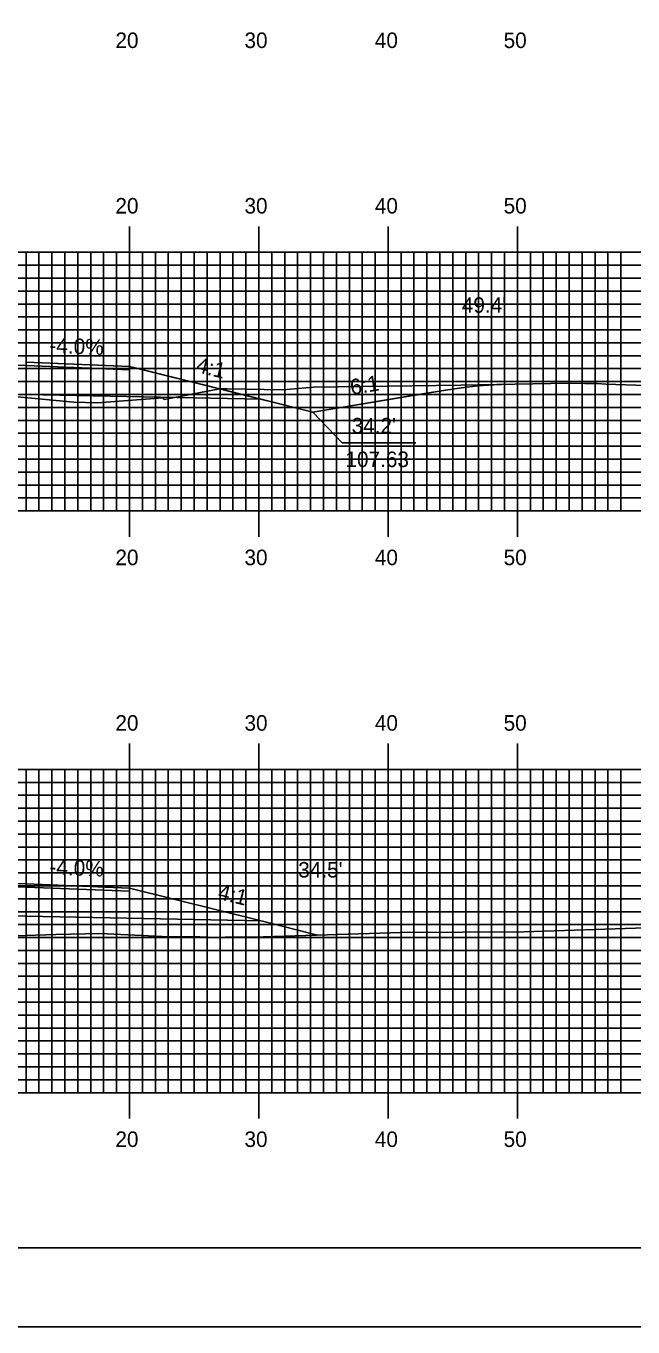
# Model space of a CAD drawing. Extents: x 1766120 to 1766463, y 442591 to 442811.
# Drawn here: x 1766297.4 to 1766344.3, y 442590.5 to 442691.2 of the extents above; entities that cross this region are included whole.
import ezdxf

# ---------------------------------------------------------------- set-up
doc = ezdxf.new("R2010")
doc.units = 0
for name, color, linetype in [('ANNOTATION', 7, 'Continuous'), ('BORDER', 7, 'Continuous'), ('D_Roadway_Centerline', 7, 'Continuous'), ('D_Roadway_Edge_Shoulder', 7, 'Continuous'), ('D_Roadway_SlopeLines', 7, 'Continuous'), ('D_Roadway_SubGrade', 7, 'Continuous'), ('D_Text_Standard', 7, 'Continuous'), ('H_V ANNOTATION', 7, 'Continuous'), ('MAJOR', 7, 'Continuous'), ('MINOR', 7, 'Continuous'), ('PLOT BOUNDARY', 7, 'Continuous'), ('S_Roadway_Centerline', 7, 'Continuous')]:
    doc.layers.add(name, color=color, linetype=linetype)

msp = doc.modelspace()

# ---------------------------------------------------------------- linework, layer by layer
at = {"layer": 'ANNOTATION'}
msp.add_lwpolyline([(1766327.54, 442658.93), (1766321.85, 442658.93), (1766319.57, 442661.3)], dxfattribs=at)
at = {"layer": 'BORDER'}
msp.add_lwpolyline([(1766135.8, 442596.67), (1766455.8, 442596.67), (1766455.8, 442806.67), (1766135.8, 442806.67)], close=True, dxfattribs=at)
at = {"layer": 'D_Roadway_Centerline'}
for points in [[(1766297.4, 442665.16), (1766305.4, 442664.84), (1766306.38, 442664.6), (1766315.57, 442662.3), (1766315.57, 442662.3), (1766315.57, 442662.3), (1766319.57, 442661.3), (1766328.22, 442662.74), (1766329.83, 442663.01), (1766331.08, 442663.19), (1766332.33, 442663.33), (1766333.58, 442663.42), (1766334.83, 442663.46)], [(1766244.99, 442619.92), (1766247.79, 442620.62), (1766253.4, 442622.03), (1766253.4, 442622.03), (1766255.22, 442622.48), (1766255.23, 442622.48), (1766261.12, 442623.95), (1766265.4, 442625.03), (1766265.4, 442625.03), (1766273.4, 442625.35), (1766273.4, 442625.35), (1766285.4, 442625.08), (1766285.8, 442625.07), (1766297.39, 442624.82), (1766297.4, 442624.82), (1766305.4, 442624.5), (1766305.4, 442624.5), (1766305.4, 442624.5), (1766315.57, 442621.95), (1766319.93, 442620.86)]]:
    msp.add_lwpolyline(points, dxfattribs=at)
at = {"layer": 'D_Roadway_Edge_Shoulder'}
for points in [[(1766297.4, 442665.16), (1766305.4, 442664.84), (1766305.4, 442664.59), (1766297.4, 442664.91)], [(1766297.4, 442624.82), (1766305.4, 442624.5), (1766305.4, 442624.25), (1766297.4, 442624.57)]]:
    msp.add_lwpolyline(points, close=True, dxfattribs=at)
at = {"layer": 'D_Roadway_SlopeLines'}
for points in [[(1766305.4, 442664.84), (1766319.57, 442661.3)], [(1766319.57, 442661.3), (1766329.83, 442663.01), (1766331.08, 442663.19), (1766332.33, 442663.33), (1766333.58, 442663.42), (1766334.83, 442663.46)], [(1766305.4, 442624.5), (1766315.57, 442621.95), (1766319.93, 442620.86)]]:
    msp.add_lwpolyline(points, dxfattribs=at)
at = {"layer": 'D_Roadway_SubGrade'}
for points in [[(1766273.4, 442663.19), (1766255.22, 442662.83), (1766265.4, 442665.37), (1766265.4, 442665.12), (1766273.4, 442665.44), (1766285.4, 442665.17), (1766297.4, 442664.91), (1766305.4, 442664.59), (1766305.4, 442664.84), (1766315.57, 442662.3), (1766297.4, 442662.66), (1766285.4, 442662.92)], [(1766273.4, 442622.85), (1766255.22, 442622.48), (1766265.4, 442625.03), (1766265.4, 442624.78), (1766273.4, 442625.1), (1766285.4, 442624.83), (1766297.4, 442624.57), (1766305.4, 442624.25), (1766305.4, 442624.5), (1766315.57, 442621.95), (1766297.4, 442622.32), (1766285.4, 442622.58)]]:
    msp.add_lwpolyline(points, close=True, dxfattribs=at)
at = {"layer": 'MAJOR'}
for p, q in [((1766305.4, 442675.67), (1766305.4, 442673.67)), ((1766315.4, 442675.67), (1766315.4, 442673.67)), ((1766325.4, 442675.67), (1766325.4, 442673.67)), ((1766335.4, 442675.67), (1766335.4, 442673.67)), ((1766145.4, 442673.67), (1766425.4, 442673.67)), ((1766145.4, 442673.67), (1766425.4, 442673.67)), ((1766305.4, 442653.67), (1766305.4, 442673.67)), ((1766315.4, 442653.67), (1766315.4, 442673.67)), ((1766325.4, 442653.67), (1766325.4, 442673.67)), ((1766335.4, 442653.67), (1766335.4, 442673.67)), ((1766145.4, 442668.67), (1766425.4, 442668.67)), ((1766145.4, 442663.67), (1766425.4, 442663.67)), ((1766145.4, 442658.67), (1766425.4, 442658.67)), ((1766145.4, 442653.67), (1766425.4, 442653.67)), ((1766145.4, 442653.67), (1766425.4, 442653.67)), ((1766305.4, 442651.66), (1766305.4, 442653.67)), ((1766315.4, 442651.66), (1766315.4, 442653.67)), ((1766325.4, 442651.66), (1766325.4, 442653.67)), ((1766335.4, 442651.66), (1766335.4, 442653.67)), ((1766305.4, 442635.67), (1766305.4, 442633.67)), ((1766315.4, 442635.67), (1766315.4, 442633.67)), ((1766325.4, 442635.67), (1766325.4, 442633.67)), ((1766335.4, 442635.67), (1766335.4, 442633.67)), ((1766145.4, 442633.67), (1766425.4, 442633.67)), ((1766145.4, 442633.67), (1766425.4, 442633.67)), ((1766305.4, 442608.67), (1766305.4, 442633.67)), ((1766315.4, 442608.67), (1766315.4, 442633.67)), ((1766325.4, 442608.67), (1766325.4, 442633.67)), ((1766335.4, 442608.67), (1766335.4, 442633.67)), ((1766145.4, 442628.67), (1766425.4, 442628.67)), ((1766145.4, 442623.67), (1766425.4, 442623.67)), ((1766145.4, 442618.67), (1766425.4, 442618.67)), ((1766145.4, 442613.67), (1766425.4, 442613.67)), ((1766145.4, 442608.67), (1766425.4, 442608.67)), ((1766145.4, 442608.67), (1766425.4, 442608.67)), ((1766305.4, 442606.66), (1766305.4, 442608.67)), ((1766315.4, 442606.66), (1766315.4, 442608.67)), ((1766325.4, 442606.66), (1766325.4, 442608.67)), ((1766335.4, 442606.66), (1766335.4, 442608.67))]:
    msp.add_line(p, q, dxfattribs=at)
at = {"layer": 'MINOR'}
for p, q in [((1766297.4, 442653.67), (1766297.4, 442673.67)), ((1766298.4, 442653.67), (1766298.4, 442673.67)), ((1766299.4, 442653.67), (1766299.4, 442673.67)), ((1766300.4, 442653.67), (1766300.4, 442673.67)), ((1766301.4, 442653.67), (1766301.4, 442673.67)), ((1766302.4, 442653.67), (1766302.4, 442673.67)), ((1766303.4, 442653.67), (1766303.4, 442673.67)), ((1766304.4, 442653.67), (1766304.4, 442673.67)), ((1766306.4, 442653.67), (1766306.4, 442673.67)), ((1766307.4, 442653.67), (1766307.4, 442673.67)), ((1766308.4, 442653.67), (1766308.4, 442673.67)), ((1766309.4, 442653.67), (1766309.4, 442673.67)), ((1766310.4, 442653.67), (1766310.4, 442673.67)), ((1766311.4, 442653.67), (1766311.4, 442673.67)), ((1766312.4, 442653.67), (1766312.4, 442673.67)), ((1766313.4, 442653.67), (1766313.4, 442673.67)), ((1766314.4, 442653.67), (1766314.4, 442673.67)), ((1766316.4, 442653.67), (1766316.4, 442673.67)), ((1766317.4, 442653.67), (1766317.4, 442673.67)), ((1766318.4, 442653.67), (1766318.4, 442673.67)), ((1766319.4, 442653.67), (1766319.4, 442673.67)), ((1766320.4, 442653.67), (1766320.4, 442673.67)), ((1766321.4, 442653.67), (1766321.4, 442673.67)), ((1766322.4, 442653.67), (1766322.4, 442673.67)), ((1766323.4, 442653.67), (1766323.4, 442673.67)), ((1766324.4, 442653.67), (1766324.4, 442673.67)), ((1766326.4, 442653.67), (1766326.4, 442673.67)), ((1766327.4, 442653.67), (1766327.4, 442673.67)), ((1766328.4, 442653.67), (1766328.4, 442673.67)), ((1766329.4, 442653.67), (1766329.4, 442673.67)), ((1766330.4, 442653.67), (1766330.4, 442673.67)), ((1766331.4, 442653.67), (1766331.4, 442673.67)), ((1766332.4, 442653.67), (1766332.4, 442673.67)), ((1766333.4, 442653.67), (1766333.4, 442673.67)), ((1766334.4, 442653.67), (1766334.4, 442673.67)), ((1766336.4, 442653.67), (1766336.4, 442673.67)), ((1766337.4, 442653.67), (1766337.4, 442673.67)), ((1766338.4, 442653.67), (1766338.4, 442673.67)), ((1766339.4, 442653.67), (1766339.4, 442673.67)), ((1766340.4, 442653.67), (1766340.4, 442673.67)), ((1766341.4, 442653.67), (1766341.4, 442673.67)), ((1766342.4, 442653.67), (1766342.4, 442673.67)), ((1766343.4, 442653.67), (1766343.4, 442673.67)), ((1766145.4, 442672.67), (1766425.4, 442672.67)), ((1766145.4, 442671.67), (1766425.4, 442671.67)), ((1766145.4, 442670.67), (1766425.4, 442670.67)), ((1766145.4, 442669.67), (1766425.4, 442669.67)), ((1766145.4, 442667.67), (1766425.4, 442667.67)), ((1766145.4, 442666.67), (1766425.4, 442666.67)), ((1766145.4, 442665.67), (1766425.4, 442665.67)), ((1766145.4, 442664.67), (1766425.4, 442664.67)), ((1766145.4, 442662.67), (1766425.4, 442662.67)), ((1766145.4, 442661.67), (1766425.4, 442661.67)), ((1766145.4, 442660.67), (1766425.4, 442660.67)), ((1766145.4, 442659.67), (1766425.4, 442659.67)), ((1766145.4, 442657.67), (1766425.4, 442657.67)), ((1766145.4, 442656.67), (1766425.4, 442656.67)), ((1766145.4, 442655.67), (1766425.4, 442655.67)), ((1766145.4, 442654.67), (1766425.4, 442654.67)), ((1766297.4, 442608.67), (1766297.4, 442633.67)), ((1766298.4, 442608.67), (1766298.4, 442633.67)), ((1766299.4, 442608.67), (1766299.4, 442633.67)), ((1766300.4, 442608.67), (1766300.4, 442633.67)), ((1766301.4, 442608.67), (1766301.4, 442633.67)), ((1766302.4, 442608.67), (1766302.4, 442633.67)), ((1766303.4, 442608.67), (1766303.4, 442633.67)), ((1766304.4, 442608.67), (1766304.4, 442633.67)), ((1766306.4, 442608.67), (1766306.4, 442633.67)), ((1766307.4, 442608.67), (1766307.4, 442633.67)), ((1766308.4, 442608.67), (1766308.4, 442633.67)), ((1766309.4, 442608.67), (1766309.4, 442633.67)), ((1766310.4, 442608.67), (1766310.4, 442633.67)), ((1766311.4, 442608.67), (1766311.4, 442633.67)), ((1766312.4, 442608.67), (1766312.4, 442633.67)), ((1766313.4, 442608.67), (1766313.4, 442633.67)), ((1766314.4, 442608.67), (1766314.4, 442633.67)), ((1766316.4, 442608.67), (1766316.4, 442633.67)), ((1766317.4, 442608.67), (1766317.4, 442633.67)), ((1766318.4, 442608.67), (1766318.4, 442633.67)), ((1766319.4, 442608.67), (1766319.4, 442633.67)), ((1766320.4, 442608.67), (1766320.4, 442633.67)), ((1766321.4, 442608.67), (1766321.4, 442633.67)), ((1766322.4, 442608.67), (1766322.4, 442633.67)), ((1766323.4, 442608.67), (1766323.4, 442633.67)), ((1766324.4, 442608.67), (1766324.4, 442633.67)), ((1766326.4, 442608.67), (1766326.4, 442633.67)), ((1766327.4, 442608.67), (1766327.4, 442633.67)), ((1766328.4, 442608.67), (1766328.4, 442633.67)), ((1766329.4, 442608.67), (1766329.4, 442633.67)), ((1766330.4, 442608.67), (1766330.4, 442633.67)), ((1766331.4, 442608.67), (1766331.4, 442633.67)), ((1766332.4, 442608.67), (1766332.4, 442633.67)), ((1766333.4, 442608.67), (1766333.4, 442633.67)), ((1766334.4, 442608.67), (1766334.4, 442633.67)), ((1766336.4, 442608.67), (1766336.4, 442633.67)), ((1766337.4, 442608.67), (1766337.4, 442633.67)), ((1766338.4, 442608.67), (1766338.4, 442633.67)), ((1766339.4, 442608.67), (1766339.4, 442633.67)), ((1766340.4, 442608.67), (1766340.4, 442633.67)), ((1766341.4, 442608.67), (1766341.4, 442633.67)), ((1766342.4, 442608.67), (1766342.4, 442633.67)), ((1766343.4, 442608.67), (1766343.4, 442633.67)), ((1766145.4, 442632.67), (1766425.4, 442632.67)), ((1766145.4, 442631.67), (1766425.4, 442631.67)), ((1766145.4, 442630.67), (1766425.4, 442630.67)), ((1766145.4, 442629.67), (1766425.4, 442629.67)), ((1766145.4, 442627.67), (1766425.4, 442627.67)), ((1766145.4, 442626.67), (1766425.4, 442626.67)), ((1766145.4, 442625.67), (1766425.4, 442625.67)), ((1766145.4, 442624.67), (1766425.4, 442624.67)), ((1766145.4, 442622.67), (1766425.4, 442622.67)), ((1766145.4, 442621.67), (1766425.4, 442621.67)), ((1766145.4, 442620.67), (1766425.4, 442620.67)), ((1766145.4, 442619.67), (1766425.4, 442619.67)), ((1766145.4, 442617.67), (1766425.4, 442617.67)), ((1766145.4, 442616.67), (1766425.4, 442616.67)), ((1766145.4, 442615.67), (1766425.4, 442615.67)), ((1766145.4, 442614.67), (1766425.4, 442614.67)), ((1766145.4, 442612.67), (1766425.4, 442612.67)), ((1766145.4, 442611.67), (1766425.4, 442611.67)), ((1766145.4, 442610.67), (1766425.4, 442610.67)), ((1766145.4, 442609.67), (1766425.4, 442609.67))]:
    msp.add_line(p, q, dxfattribs=at)
at = {"layer": 'PLOT BOUNDARY'}
msp.add_lwpolyline([(1766119.61, 442590.55), (1766459.61, 442590.55), (1766459.61, 442810.55), (1766119.61, 442810.55)], close=True, dxfattribs=at)
at = {"layer": 'S_Roadway_Centerline'}
for points in [[(1766296.45, 442662.52), (1766301.09, 442662.08), (1766302.92, 442662.03), (1766307.97, 442662.42), (1766308.08, 442662.29), (1766311.43, 442662.93), (1766312.26, 442663.08), (1766312.47, 442663.1), (1766312.95, 442663.12), (1766317.25, 442663.02), (1766319.62, 442663.24), (1766331.01, 442663.4), (1766337.98, 442663.51), (1766339.56, 442663.54), (1766340.6, 442663.53), (1766341.58, 442663.51), (1766342.23, 442663.48), (1766345.34, 442663.37)], [(1766290.31, 442620.59), (1766299.69, 442620.9), (1766303.12, 442620.97), (1766307.93, 442620.76), (1766310.83, 442620.73), (1766311.48, 442620.71), (1766312.19, 442620.67), (1766312.34, 442620.68), (1766312.35, 442620.67), (1766312.79, 442620.71), (1766315.76, 442620.73), (1766326.4, 442621.07), (1766335.9, 442621.11), (1766345.3, 442621.41)]]:
    msp.add_lwpolyline(points, dxfattribs=at)

# ---------------------------------------------------------------- texts
at = {"layer": 'ANNOTATION'}
for s, rotation, p in [('-4.0%', 357.7094, (1766299.19, 442665.89)), ('4:1', 345.9666, (1766310.48, 442664.43)), ('6:1', 9.4611, (1766322.57, 442662.63)), ('-4.0%', 357.7094, (1766299.19, 442625.55)), ('4:1', 345.9623, (1766312.17, 442623.67))]:
    msp.add_text(s, height=1.2, rotation=rotation, dxfattribs=at).set_placement(p)
for s, p in [("34.2'", (1766322.58, 442659.66)), ('107.63', (1766322.1, 442657.06))]:
    msp.add_text(s, height=1.2, dxfattribs=at).set_placement(p)
at = {"layer": 'D_Text_Standard'}
for s, p in [("49.4'", (1766331.1, 442668.99)), ("34.5'", (1766318.45, 442625.31))]:
    msp.add_text(s, height=1.2, dxfattribs=at).set_placement(p)
at = {"layer": 'H_V ANNOTATION'}
for s, p in [('20', (1766304.31, 442689.47)), ('30', (1766314.29, 442689.47)), ('40', (1766324.37, 442689.47)), ('50', (1766334.33, 442689.47)), ('20', (1766304.31, 442676.67)), ('30', (1766314.29, 442676.67)), ('40', (1766324.37, 442676.67)), ('50', (1766334.33, 442676.67)), ('20', (1766304.31, 442649.47)), ('30', (1766314.29, 442649.47)), ('40', (1766324.37, 442649.47)), ('50', (1766334.33, 442649.47)), ('20', (1766304.31, 442636.67)), ('30', (1766314.29, 442636.67)), ('40', (1766324.37, 442636.67)), ('50', (1766334.33, 442636.67)), ('20', (1766304.31, 442604.47)), ('30', (1766314.29, 442604.47)), ('40', (1766324.37, 442604.47)), ('50', (1766334.33, 442604.47))]:
    msp.add_text(s, height=1.2, dxfattribs=at).set_placement(p)

doc.saveas('drawing.dxf')
